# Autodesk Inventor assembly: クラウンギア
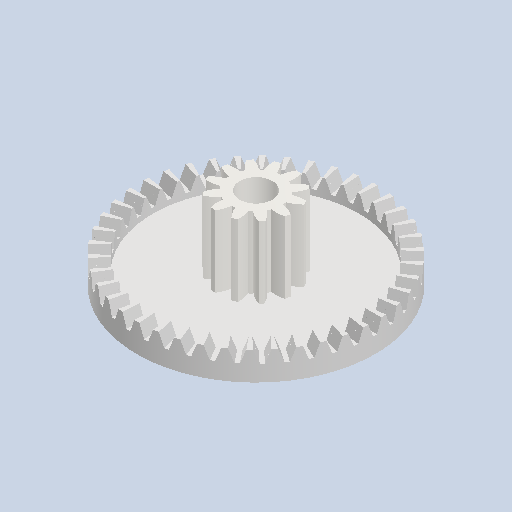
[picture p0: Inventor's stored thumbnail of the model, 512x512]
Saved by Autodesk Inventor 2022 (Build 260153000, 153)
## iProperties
Created: 2024-12
Part Number: クラウンギア
Document SubType Name: Assembly
Designer: jsat7
Author: jsat7
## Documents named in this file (3)
- C:\Users\jsat7\OneDrive\デスクトップ\CAD 長田\クラウンギア.iam
- C:\Users\jsat7\OneDrive\デスクトップ\CAD 長田\クラウンギア 土台.ipt
- C:\Users\jsat7\OneDrive\デスクトップ\CAD 長田\12Tギア　クラウンギア.ipt
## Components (2 placed, 2 different names)
1. クラウンギア 土台:1 — リジッド:1
2. 平歯車1:1 — リジッド:1
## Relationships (1: WeldJoint 1)
- リジッド:1 [WeldJoint]: クラウンギア 土台:1 ↔ 平歯車1:1
